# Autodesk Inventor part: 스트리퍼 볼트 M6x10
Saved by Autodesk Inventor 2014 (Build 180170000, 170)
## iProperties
Created: 2025-02
Part Number: 스트리퍼 볼트 M6x10
Material: 일반
Document SubType Name: Modeling
Designer: dg
Density: 1 g/cm^3
Appearance: 기본값
Author: dg
Author: jhkim
Description: 홈붙이 냄비머리 나사
Creation Date: 2025-02-05
Sending System: Autodesk Inventor 2025
Preprocessor: ST-DEVELOPER v20
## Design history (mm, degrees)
node "스트리퍼 볼트 M6x101"
body "Solid1"
node "기준1"
